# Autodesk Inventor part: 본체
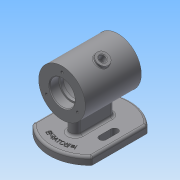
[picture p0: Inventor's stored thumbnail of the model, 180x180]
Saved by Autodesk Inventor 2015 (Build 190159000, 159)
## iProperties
Created: 2022-02
Part Number: 본체
Material: 일반
Document SubType Name: Modeling
Designer: 학생용
Density: 1 g/cm^3
Appearance: 기본값
Mass: 183.432 g
Surface Area: 489.776 cm^2
Volume: 183.432 cm^3
Author: 학생용
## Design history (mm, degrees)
sketch "스케치1"
  geometry: L1 (0, 0)-(72, 0); L2 (0, 0)-(0, 30); L3 (0, 30)-(72, 30); L4 (72, 30)-(72, 0); L5 (0, 16)-(12, 16); L6 (12, 16)-(12, 14); L7 (12, 14)-(16, 14); L8 (16, 14)-(16, 25); L9 (16, 25)-(56, 25); L10 (56, 25)-(56, 14); L11 (56, 14)-(60, 14); L12 (60, 14)-(60, 16); L13 (60, 16)-(72, 16)
  constraints: 26 end point, 8 perpendicular, 6 point on line, 2 horizontal, 1 collinear, 1 vertical
  dimensions: "d0" = 72 distance of L1.start L1.end; "d1" = 60 diameter of L3 L1; "d2" = 40 distance of L8.end L9.end; "d3" = 12 distance of L5.start L5.end; "d4" = 4 distance of L6.end L7.end; "d5" = 50 diameter of L9 L1; "d6" = 28 diameter of L7 L1; "d7" = 32 diameter of L5 L1
revolve "회전1" sketch "스케치1" stored, may be unused: angle "d8" = 90 deg
chamfer "모따기1" distance "d9" = 1; stored, may be unused: second distance "d10" = 2, angle "d11" = 45 deg
fillet "모깎기1" dims "d12" = 3
fillet "모깎기2" dims "d13" = 0.3
node "작업 평면1"
sketch "스케치2"
  geometry: L1 (0, 0)-(0, 30); L2 (0, 0)-(30, 0); L3 (0, 0)-(16.5, 28.579); A1 r 30 centre (0, 0) between (0, 30) and (30, 0) reference
  constraints: 6 end point, 2 point on circle, 1 perpendicular, 1 vertical
  dimensions: "d14" = 30 deg angle of L1 L3; "d15" = 33 distance of L3.start L3.end
node "작업 평면2"
sketch "스케치3"
  geometry: C1 r 8 at (0, 0); 1 further point
  constraints: 1 centre point
  dimensions: "d16" = 16 diameter of C1
extrude "돌출1" join sketch "스케치3" stored distance "d17" = 10; taper "d18" = 0 deg
sketch "스케치4"
  geometry: C1 r 4 at (0, 0); 1 further point
  constraints: 1 centre point
  dimensions: "d19" = 8 diameter of C1
extrude "돌출2" cut sketch "스케치4" stored distance "d20" = 10; taper "d21" = 0 deg
fillet "모깎기3" dims "d22" = 1
sketch "스케치5"
  geometry: L1 (0, 0)-(-23, 0); L2 (0, 0)-(23, 0); L3 (0, 0)-(19.919, -11.5); L4 (0, 0)-(-19.919, -11.5); A1 r 23 centre (0, 0) between (0, 23) and (-23, 0); 3 further points
  constraints: 8 end point, 5 point on circle, 3 coincident, 2 horizontal, 1 centre point
  dimensions: "d26" = 46 diameter of A1; "d27" = 30 deg angle of L1 L4; "d28" = 30 deg angle of L2 L3
hole "구멍1" sketch "스케치5" at (0, 23), (-19.919, -11.5), (19.919, -11.5) diameter "d29" = 3.242; stored, may be unused: countersink angle "d33" = 90 deg, drill point angle "d35" = 118 deg; dims "d30" = 8, "d31" = 4, "d32" = 2, "d34" = 10
node "작업 평면3"
sketch "스케치6"
  geometry: L1 (42, 36)-(-42, 36) reference; L2 (-38, 0.504)-(-38, 71.496); L3 (38, 71.496)-(38, 0.504); A1 r 52 centre (0, 36) between (-38, 0.504) and (38, 0.504); A2 r 52 centre (0, 36) between (38, 71.496) and (-38, 71.496); 1 further point
  constraints: 4 end point, 4 point on circle, 2 centre point, 1 midpoint, 1 parallel, 1 vertical, 1 vertical alignment
  dimensions: "d38" = 76 distance between parallel lines of L3 L2; "d39" = 38 distance from line of A1.centre L3
extrude "돌출3" join sketch "스케치6" distance "d40" = 10; taper "d41" = 0 deg
sketch "스케치7"
  geometry: L1 (-38, 0.504)-(-38, 71.496) reference; L2 (0, 55)-(0, 17); L3 (-7, 55)-(-7, 17); L4 (7, 17)-(7, 55); L5 (-24, 43.5)-(-24, 28.5); L6 (-28.5, 43.5)-(-28.5, 28.5); L7 (-19.5, 28.5)-(-19.5, 43.5); L8 (24, 43.5)-(24, 28.5); L9 (19.5, 43.5)-(19.5, 28.5); L10 (28.5, 28.5)-(28.5, 43.5); C1 r 42.5 at (0, 36); A1 r 7 centre (0, 55) between (7, 55) and (-7, 55); A2 r 7 centre (0, 17) between (-7, 17) and (7, 17); A3 r 4.5 centre (-24, 43.5) between (-19.5, 43.5) and (-28.5, 43.5); A4 r 4.5 centre (-24, 28.5) between (-28.5, 28.5) and (-19.5, 28.5); A5 r 4.5 centre (24, 43.5) between (28.5, 43.5) and (19.5, 43.5); A6 r 4.5 centre (24, 28.5) between (19.5, 28.5) and (28.5, 28.5); 4 further points
  constraints: 24 end point, 12 point on circle, 12 tangent, 7 centre point, 5 parallel, 4 midpoint, 3 horizontal alignment, 2 vertical, 1 vertical alignment, 1 other
  dimensions: "d42" = 85 diameter of C1; "d43" = 14 distance between parallel lines of L4 L3; "d44" = 38 distance of L2.start L2.end; "d45" = 15 distance of L5.start L5.end; "d46" = 9 distance between parallel lines of L7 L6; "d47" = 9 distance between parallel lines of L10 L9; "d48" = 48 distance between parallel lines of L8 L5; "d49" = 24 distance between parallel lines of L2 L8
extrude "돌출4" cut sketch "스케치7" distance "d50" = 10; taper "d51" = 0 deg
extrude "돌출5" join sketch "스케치7" stored distance "d52" = 10; taper "d53" = 0 deg
feature "엠보싱1" dims "d0" = 72, "d1" = 60, "d2" = 40, "d3" = 12, "d4" = 4, "d5" = 50, "d6" = 28, "d7" = 32, "d54" = 0.5, "d55" = 0
fillet "모깎기4" dims "d56" = 3
fillet "모깎기5" dims "d57" = 3
fillet "모깎기6" dims "d58" = 3
fillet "모깎기7" dims "d59" = 1
node "솔리드1"
mirror "대칭1"
other parameters: "d36" = -62, "d37" = 104
